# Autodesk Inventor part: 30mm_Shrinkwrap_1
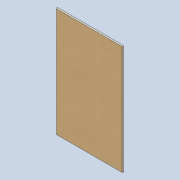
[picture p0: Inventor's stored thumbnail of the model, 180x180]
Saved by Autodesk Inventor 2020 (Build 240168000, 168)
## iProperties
Created: 2020-11
Part Number: 30mm_Shrinkwrap_1
Material: Generic
Document SubType Name: Modeling
Designer: Yolande
Density: 1 g/cm^3
Appearance: Default
description: 0:0:Lambdaboard 30mm Kraft
manufacturer: 0:0:Lambdaboard T/A Rigifoam
model: 0:0:
url: 0:0:www.lambdaboard.com
Author: Yolande
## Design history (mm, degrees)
derived "30mm.iam"
body "Solid1"
node "Lambdaboard 30mm Kraft.ipt:1" dims "d0" = 10
